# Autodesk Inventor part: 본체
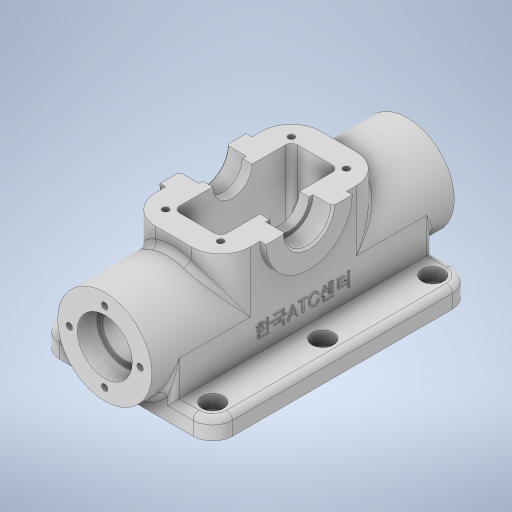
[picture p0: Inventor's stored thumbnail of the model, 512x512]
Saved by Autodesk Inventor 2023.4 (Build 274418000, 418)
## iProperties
Created: 2024-06
Part Number: 본체
Material: 일반
Document SubType Name: Modeling
Designer: edu-40
Density: 1 g/cm^3
Appearance: 기본값
Author: edu-40
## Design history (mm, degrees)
sketch "스케치1"
  geometry: L1 (27, -24)-(-27, -24); L2 (-42, -9)-(-42, 9); L3 (-27, 24)-(27, 24); L4 (42, 9)-(42, -9); A1 r 15 centre (27, -9) between (27, -24) and (42, -9); A2 r 15 centre (27, 9) between (42, 9) and (27, 24); A3 r 15 centre (-27, 9) between (-27, 24) and (-42, 9); A4 r 15 centre (-27, -9) between (-42, -9) and (-27, -24); 6 further points
  constraints: 8 end point, 8 point on circle, 8 tangent, 6 point on line, 4 centre point, 3 equal radius, 2 midpoint, 2 parallel, 1 horizontal, 1 horizontal alignment, 1 perpendicular, 1 vertical alignment
  dimensions: "d0" = 84 distance of point (42, -24) point (-42, -24); "d1" = 48 distance of point (42, 24) point (42, -24); "d2" = 15 radius of A1
extrude "돌출1" new body sketch "스케치1" distance "d3" = 59; taper "d4" = 0 deg
sketch "스케치2"
  geometry: L1 (56, -44)-(-56, -44); L2 (-66, -34)-(-66, 34); L3 (-56, 44)-(56, 44); L4 (66, 34)-(66, -34); A1 r 10 centre (56, -34) between (56, -44) and (66, -34); A2 r 10 centre (-56, -34) between (-66, -34) and (-56, -44); A3 r 10 centre (-56, 34) between (-56, 44) and (-66, 34); A4 r 10 centre (56, 34) between (66, 34) and (56, 44); 6 further points
  constraints: 8 end point, 8 point on circle, 8 tangent, 6 point on line, 4 centre point, 3 equal radius, 2 midpoint, 2 parallel, 1 horizontal, 1 horizontal alignment, 1 perpendicular, 1 vertical alignment
  dimensions: "d5" = 132 distance of point (66, -44) point (-66, -44); "d6" = 88 distance of point (66, 44) point (66, -44); "d7" = 10 radius of A1
extrude "돌출2" join sketch "스케치2" distance "d8" = 10; taper "d9" = 0 deg
sketch "스케치3"
  geometry: L1 (0, 34)-(0, -34) reference; L2 (10, -24)-(59, -24) reference; L3 (28, -24)-(10, -24); L4 (10, 24)-(59, 24) reference; L5 (28, 24)-(10, 24); L6 (10, -24)-(10, 24); L7 (10, 34)-(10, -34) reference; A1 r 24 centre (28, 0) between (28, -24) and (28, 24); 3 further points
  constraints: 6 end point, 3 collinear, 2 point on circle, 2 point on line, 1 centre point, 1 horizontal alignment
  dimensions: "d10" = 48 diameter of A1; "d11" = 28 distance from line of L1 A1.centre
extrude "돌출3" join sketch "스케치3" stored distance "d12" = 154; taper "d13" = 0 deg
extrude "돌출4" join sketch "스케치3" stored distance "d14" = 132; taper "d15" = 0 deg
sketch "스케치4"
  geometry: L1 (27, 59)-(-27, 59) reference; L2 (-22, 59)-(22, 59); A1 r 22 centre (0, 59) between (-22, 59) and (22, 59); 2 further points
  constraints: 2 end point, 2 midpoint, 2 point on circle, 2 point on line, 1 centre point, 1 vertical alignment
  dimensions: "d16" = 44 diameter of A1
extrude "돌출5" join sketch "스케치4" stored distance "d17" = 54; taper "d18" = 0 deg
sketch "스케치5"
  geometry: L1 (22, 59)-(-22, 59) reference; L2 (-12, 59)-(12, 59); A1 r 12 centre (0, 59) between (-12, 59) and (12, 59); 1 further point
  constraints: 2 end point, 2 point on circle, 2 point on line, 1 centre point, 1 midpoint
  dimensions: "d19" = 24 diameter of A1
extrude "돌출6" cut sketch "스케치5" distance "d20" = 10; taper "d21" = 0 deg
sketch "스케치6"
  geometry: L1 (22, 59)-(-22, 59) reference; L2 (-12, 59)-(12, 59); L3 (-56, 0)-(56, 0) reference; A1 r 12 centre (0, 59) between (-12, 59) and (12, 59); 3 further points
  constraints: 3 midpoint, 2 end point, 2 point on circle, 2 point on line, 1 centre point, 1 vertical alignment
  dimensions: "d22" = 24 diameter of A1
extrude "돌출7" cut sketch "스케치6" distance "d23" = 10; taper "d24" = 0 deg
sketch "스케치7"
  geometry: L1 (-12, 59)-(12, 59) reference; L2 (-10, 59)-(10, 59); L3 (-56, 0)-(56, 0) reference; A1 r 10 centre (0, 59) between (-10, 59) and (10, 59); 3 further points
  constraints: 3 midpoint, 2 end point, 2 point on circle, 2 point on line, 1 centre point, 1 vertical alignment
  dimensions: "d25" = 20 diameter of A1
extrude "돌출8" cut sketch "스케치7" extent not by distance; stored distance "d26" = 0; taper "d27" = 0 deg
sketch "스케치8"
  geometry: L1 (27, -12)-(-27, -12); L2 (-30, -9)-(-30, 9); L3 (-27, 12)-(27, 12); L4 (30, 9)-(30, -9); A1 r 3 centre (27, -9) between (27, -12) and (30, -9); A2 r 3 centre (27, 9) between (30, 9) and (27, 12); A3 r 3 centre (-27, 9) between (-27, 12) and (-30, 9); A4 r 3 centre (-27, -9) between (-30, -9) and (-27, -12); 6 further points
  constraints: 8 end point, 8 point on circle, 8 tangent, 6 point on line, 4 centre point, 3 equal radius, 2 midpoint, 2 parallel, 1 horizontal, 1 horizontal alignment, 1 perpendicular, 1 vertical alignment
  dimensions: "d28" = 60 distance of point (30, -12) point (-30, -12); "d29" = 24 distance of point (-30, -12) point (-30, 12); "d30" = 3 radius of A1 (derived)
extrude "돌출9" cut sketch "스케치8" extent not by distance; stored distance "d31" = 0; taper "d32" = 0 deg
sketch "스케치9"
  geometry: C1 r 14 at (0, 0); 1 further point
  constraints: 1 centre point
  dimensions: "d33" = 28 diameter of C1
extrude "돌출10" cut sketch "스케치9" distance "d34" = 10; taper "d35" = 0 deg
sketch "스케치10"
  geometry: C1 r 14 at (0, 0); 1 further point
  constraints: 1 centre point
  dimensions: "d36" = 28 diameter of C1
extrude "돌출11" cut sketch "스케치10" distance "d37" = 10; taper "d38" = 0 deg
sketch "스케치11"
  geometry: C1 r 11 at (0, 0); 1 further point
  constraints: 1 centre point
  dimensions: "d39" = 22 diameter of C1
extrude "돌출12" cut sketch "스케치11" extent not by distance; stored distance "d40" = 0; taper "d41" = 0 deg
chamfer "모따기1" distance "d42" = 1; stored, may be unused: second distance "d43" = 2, angle "d44" = 45 deg
chamfer "모따기2" distance "d45" = 1; stored, may be unused: second distance "d46" = 2, angle "d47" = 45 deg
fillet "모깎기1" dims "d48" = 3
sketch "스케치12"
  geometry: C1 r 24 at (0, 0) reference; A1 r 18 centre (0, 0) between (0, 18) and (18, 0); 3 further points
  constraints: 4 point on circle, 2 horizontal alignment, 2 vertical alignment, 1 centre point, 1 concentric
  dimensions: "d56" = 36 diameter of A1
hole "구멍1" sketch "스케치12" at (0, 18), (-18, 0), (18, 0), (0, -18) diameter "d49" = 3.242; stored, may be unused: countersink angle "d53" = 90 deg, drill point angle "d55" = 118 deg; dims "d50" = 8, "d51" = 4, "d52" = 2, "d54" = 10
sketch "스케치13"
  geometry: C1 r 24 at (0, 0) reference; A1 r 18 centre (0, 0) between (0, 18) and (18, 0); 3 further points
  constraints: 4 point on circle, 2 horizontal alignment, 2 vertical alignment, 1 centre point, 1 concentric
  dimensions: "d64" = 36 diameter of A1
hole "구멍2" sketch "스케치13" at (0, 18), (-18, 0), (18, 0), (0, -18) diameter "d57" = 3.242; stored, may be unused: countersink angle "d61" = 90 deg, drill point angle "d63" = 118 deg; dims "d58" = 8, "d59" = 4, "d60" = 2, "d62" = 10
sketch "스케치14"
  geometry: L1 (56, 44)-(-56, 44) reference; L2 (-66, 34)-(-66, 27) reference; 2 further points
  dimensions: "d72" = 10 distance from line of point (-56, 34) L1; "d73" = 10 distance from line of L2 point (-56, 34)
hole "구멍3" sketch "스케치14" at (-56, 34) diameter "d65" = 6.6; stored, may be unused: countersink angle "d69" = 90 deg, drill point angle "d71" = 0 deg; dims "d66" = 8, "d67" = 11, "d68" = 6.6, "d70" = 10
sketch "스케치15"
  geometry: L1 (-56, -44)-(56, -44) reference; L2 (-66, -21)-(-66, -34) reference; 6 further points
  constraints: 3 vertical alignment, 2 horizontal alignment
  dimensions: "d81" = 10 distance from line of L1 point (-56, -34); "d82" = 10 distance from line of L2 point (-56, -34); "d83" = 112 distance of point (56, -34) point (-56, -34)
hole "구멍4" sketch "스케치15" at (0, 33.726), (56, 33.946), (56, -34), (0, -34), (-56, -34) diameter "d74" = 6.6; stored, may be unused: countersink angle "d78" = 90 deg, drill point angle "d80" = 118 deg; dims "d75" = 6, "d76" = 11, "d77" = 6.6, "d79" = 8
sketch "스케치16"
  geometry: 5 further points
  constraints: 2 horizontal alignment, 2 vertical alignment
  dimensions: "d91" = 32 horizontal distance of point (0, 0) point (-32, 14); "d92" = 14 vertical distance of point (0, 0) point (32, 14); "d93" = 14 vertical distance of point (0, 0) point (-32, -14); "d94" = 32 horizontal distance of point (0, 0) point (32, -14)
hole "구멍5" sketch "스케치16" at (-32, 14), (-32, -14), (32, -14), (32, 14) diameter "d84" = 3.242; stored, may be unused: countersink angle "d88" = 90 deg, drill point angle "d90" = 118 deg; dims "d85" = 8, "d86" = 11, "d87" = 6.6, "d89" = 10
sketch "스케치17"
  geometry: L1 (-56, -59)-(56, -59) reference; 3 further points
  constraints: 1 midpoint, 1 vertical alignment, 1 other
  dimensions: "d95" = 20 distance from line of L1 point (0, -39)
feature "엠보싱1" sketch "스케치17" dims "d0" = 84, "d1" = 48, "d2" = 15, "d5" = 132, "d6" = 88, "d7" = 10, "d96" = 0.5, "d97" = 0
node "솔리드1"
feature "A9D066F2-1C7D-4E18-AEED-F7BC21143FA4" dims "d49" = 3.242, "d50" = 8, "d51" = 4, "d52" = 2, "d53" = 90 deg, "d54" = 10, "d55" = 118 deg
